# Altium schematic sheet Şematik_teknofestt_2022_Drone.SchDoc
size A4; SheetNumber: 1; SheetTotal: 2
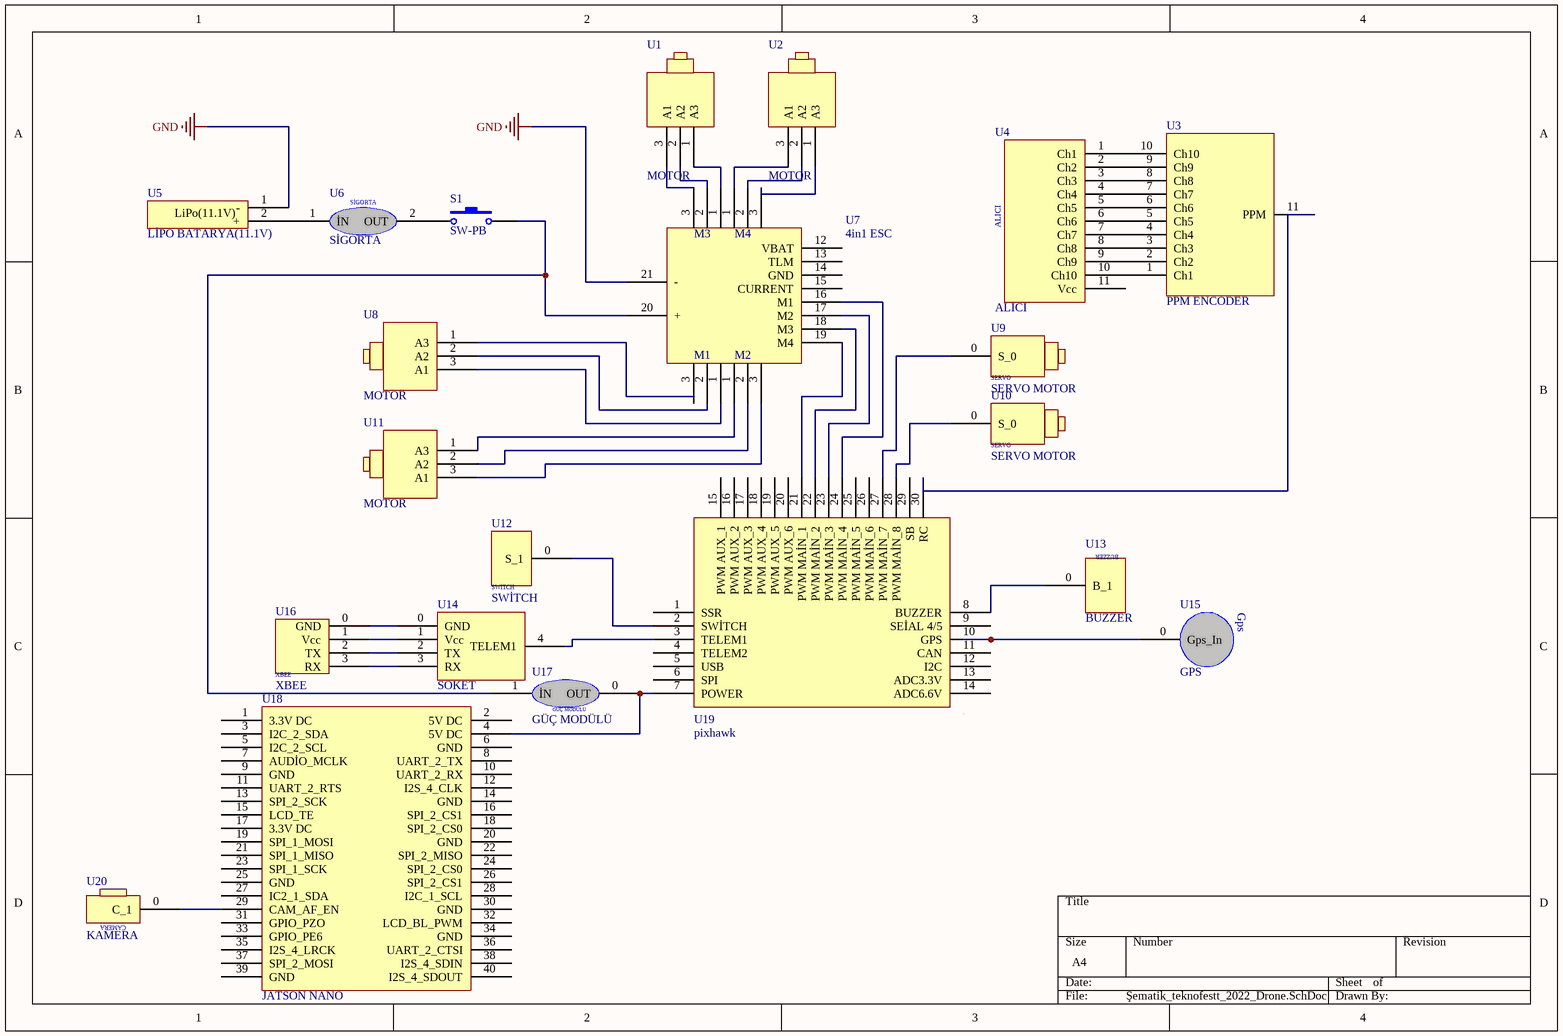
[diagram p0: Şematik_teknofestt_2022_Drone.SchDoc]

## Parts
S1  SW-PB  [SPST-2]
U1  MOTOR
U2  MOTOR
U3  PPM ENCODER
U4  ALICI
U5  LİPO BATARYA(11.1V)
U6  SİGORTA
U7  4in1 ESC
U8  MOTOR
U9  SERVO MOTOR
U10  SERVO MOTOR
U11  MOTOR
U12  SWİTCH
U13  BUZZER
U14  SOKET
U15  GPS
U16  XBEE
U17  GÜÇ MODÜLÜ
U18  JATSON NANO
U19  pixhawk
U20  KAMERA

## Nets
GND: U5.1(-) U7.21(-)
NetS1_2: S1.2 U7.20(+) U17.1(İN)
NetU1_1: U1.1(A3) U7.1
NetU1_2: U1.2(A2) U7.2
NetU1_3: U1.3(A1) U7.3
NetU2_1: U2.1(A3) U7.3
NetU2_2: U2.2(A2) U7.2
NetU2_3: U2.3(A1) U7.1
NetU3_1: U3.1(Ch1) U4.10(Ch10)
NetU3_2: U3.2(Ch2) U4.9(Ch9)
NetU3_3: U3.3(Ch3) U4.8(Ch8)
NetU3_4: U3.4(Ch4) U4.7(Ch7)
NetU3_5: U3.5(Ch5) U4.6(Ch6)
NetU3_6: U3.6(Ch6) U4.5(Ch5)
NetU3_7: U3.7(Ch7) U4.4(Ch4)
NetU3_8: U3.8(Ch8) U4.3(Ch3)
NetU3_9: U3.9(Ch9) U4.2(Ch2)
NetU3_10: U3.10(Ch10) U4.1(Ch1)
NetU3_11: U3.11(PPM) U19.30(RC)
NetU5_2: U5.2(+) U6.1(İN)
NetU7_1: U7.1 U8.3(A1)
NetU7_1: U7.1 U11.1(A3)  [a separate net that carries the same name]
NetU7_2: U7.2 U8.2(A2)
NetU7_2: U7.2 U11.2(A2)  [a separate net that carries the same name]
NetU7_3: U7.3 U11.3(A1)
NetU7_16: U7.16(M1) U19.24(PWM_MAİN_4)
NetU7_17: U7.17(M2) U19.23(PWM_MAİN_3)
NetU7_18: U7.18(M3) U19.22(PWM_MAİN_2)
NetU7_19: U7.19(M4) U19.21(PWM_MAİN_1)
NetU9_0: U9.0(S_0) U19.27(PWM_MAİN_7)
NetU10_0: U10.0(S_0) U19.28(PWM_MAİN_8)
NetU12_0: U12.0(S_1) U19.2(SWİTCH)
NetU13_0: U13.0(B_1) U19.8(BUZZER)
NetU14_0: U14.0(GND) U16.0(GND)
NetU14_1: U14.1(Vcc) U16.1(Vcc)
NetU14_2: U14.2(TX) U16.2(TX)
NetU14_3: U14.3(RX) U16.3(RX)
NetU14_4: U14.4(TELEM1) U19.3(TELEM1)
NetU15_0: U15.0(Gps_In) U19.10(GPS)
NetU17_0: U17.0(OUT) U18.4(5V_DC) U19.7(POWER)
NetU18_29: U18.29(CAM_AF_EN) U20.0(C_1)

Not connected (* = marked no-connect by the designer): S1 1; U4 11(Vcc); U6 2(OUT); U7 12(VBAT) 13(TLM) 14(GND) 15(CURRENT); U8 1(A3); U18 1(3.3V_DC) 2(5V_DC) 3(I2C_2_SDA) 5(I2C_2_SCL) 6(GND) 7(AUDİO_MCLK) 8(UART_2_TX) 9(GND) 10(UART_2_RX) 11(UART_2_RTS) 12(I2S_4_CLK) 13(SPI_2_SCK) 14(GND) 15(LCD_TE) 16(SPI_2_CS1) 17(3.3V_DC) 18(SPI_2_CS0) 19(SPI_1_MOSI) 20(GND) 21(SPI_1_MISO) 22(SPI_2_MISO) 23(SPI_1_SCK) 24(SPI_2_CS0) 25(GND) 26(SPI_2_CS1) 27(IC2_1_SDA) 28(I2C_1_SCL) 30(GND) 31(GPIO_PZO) 32(LCD_BL_PWM) 33(GPIO_PE6) 34(GND) 35(I2S_4_LRCK) 36(UART_2_CTSI) 37(SPI_2_MOSI) 38(I2S_4_SDIN) 39(GND) 40(I2S_4_SDOUT); U19 1(SSR) 4(TELEM2) 5(USB) 6(SPI) 9(SEİAL_4/5) 11(CAN) 12(I2C) 13(ADC3.3V) 14(ADC6.6V) 15(PWM_AUX_1) 16(PWM_AUX_2) 17(PWM_AUX_3) 18(PWM_AUX_4) 19(PWM_AUX_5) 20(PWM_AUX_6) 25(PWM_MAİN_5) 26(PWM_MAİN_6) 29(SB)

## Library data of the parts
S1 = SW-PB: Switch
